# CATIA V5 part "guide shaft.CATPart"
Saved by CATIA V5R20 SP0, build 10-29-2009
Part number: guide shaft
Bounding box of the stored display mesh (mm): x -400 to 614.937, y -80 to -20, z 61.829 to 675.233
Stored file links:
  E:\Ehsan\CATIA\CATIA Course\Basic\Practices\Assembly\2\guide shaft.CATPart
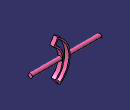
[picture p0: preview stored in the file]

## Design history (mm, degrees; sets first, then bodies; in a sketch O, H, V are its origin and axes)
Body1 (main body)
  DatumSurface1
  DatumCurve1 to DatumCurve4
  Plane1: type Offset, RefPlane zx-plane, Offset 50, reversed
  Sketch1 on Plane1, origin (0, -50, 0), H (-1, 0, 0), V (0, 0, 1)
    line L1 (-281.5428, 155.212) -> (-216.1551, 61.8287)
    arc A1 centre (-424.937, 360) radius 364 from (-216.1551, 61.8287) to (-242.937, 675.2332) ccw
    line L2 (-299.937, 576.5064) -> (-242.937, 675.2332)
    arc A2 centre (-424.937, 360) radius 250 from (-281.5428, 155.212) to (-299.937, 576.5064) ccw
    arc A3 centre (-424.937, 360) radius 270 from (-254.1137, 150.9081) to (-272.9873, 583.1845) ccw
    line L3 (-254.1137, 150.9081) -> (-211.5774, 90.1599)
    arc A4 centre (-424.937, 360) radius 344 from (-211.5774, 90.1599) to (-235.9074, 647.4088) ccw
    line L4 (-272.9873, 583.1845) -> (-235.9074, 647.4088)
  Pad1: profile Sketch1, direction (0, 1, 0), length 30, mirrored extent
  DatumCurve5
  DatumSurface2
  Sketch2 on yz-plane, origin (0, 0, 0), H (0, 1, 0), V (0, 0, 1)
    circle A1 centre (-50, 360) radius 30
    reference projected circle E1 centre (-50, 360) radius 30 from edge of DatumCurve5
    coincidence: A1 E1
  Pad2: profile Sketch2, direction (1, 0, 0), up to the existing solid (limit type 2), opposite side length 400
  Sketch3 on face of DatumSurface2, origin (364.937, 0, 0), H (0, -1, 0), V (0, 0, 1)
    circle A1 centre (50, 360) radius 30
    reference projected circle E1 centre (50, 360) radius 30 from edge [start face of Pad2 | face of Pad2 from Sketch2.A1]
    coincidence: A1 E1
  Pad3: profile Sketch3, direction (-1, 0, 0), up to the existing solid (limit type 2), opposite side length 250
